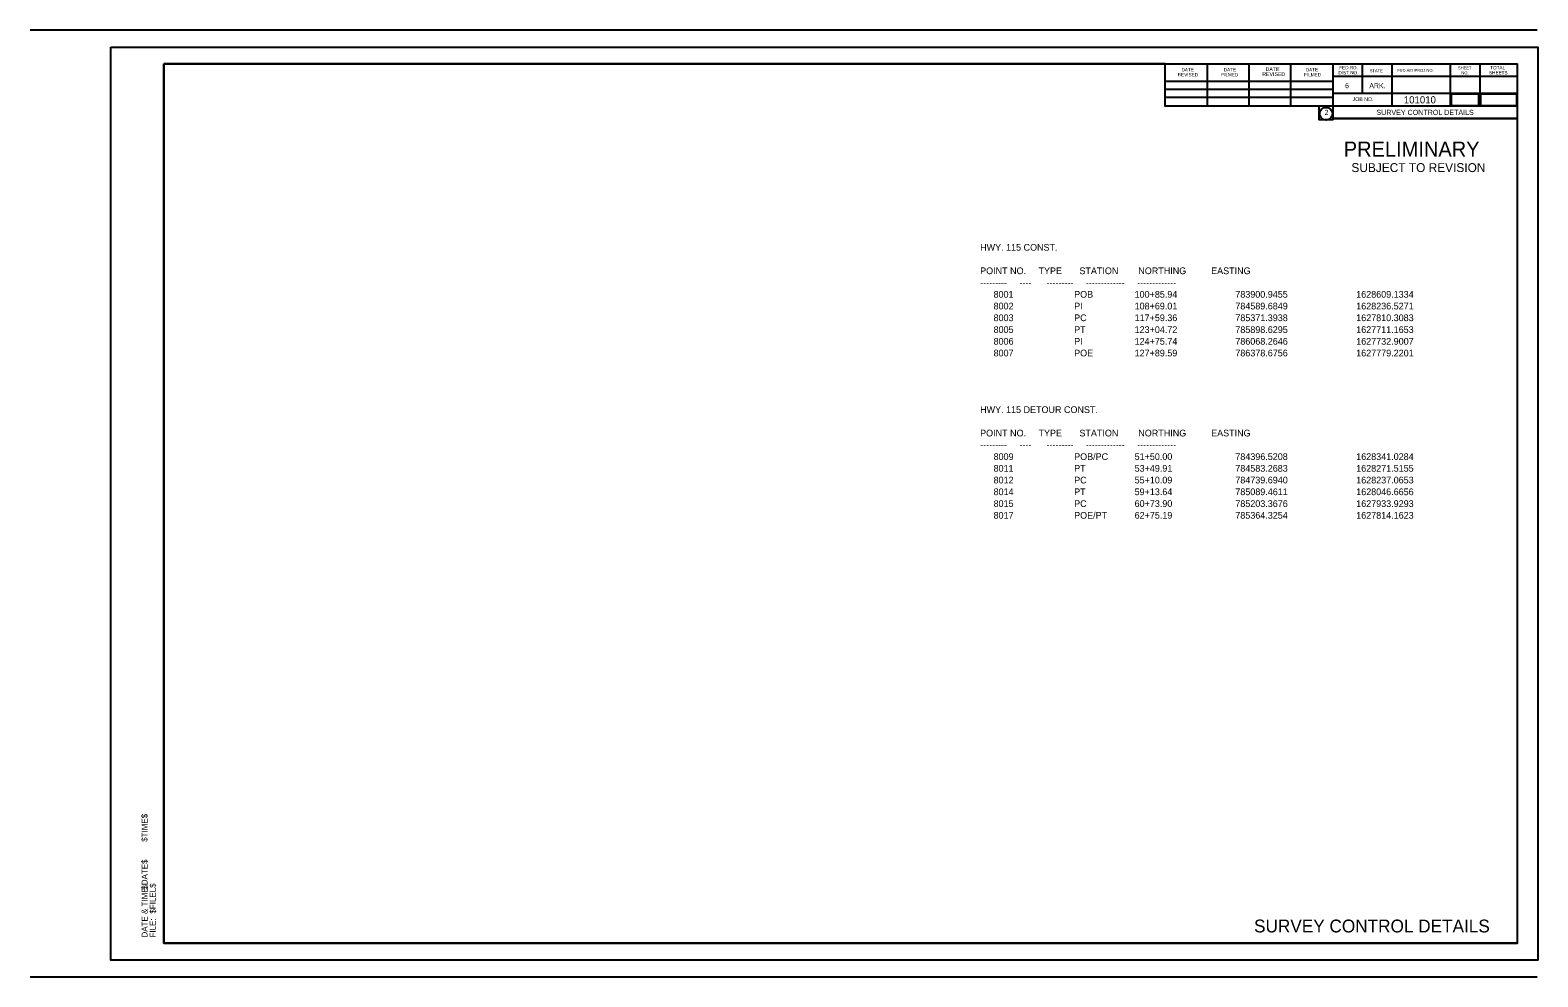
# Model space of a CAD drawing. Extents: x 3698 to 9589, y 10000 to 11106.
# Drawn here: x 3698 to 5459, y 10000 to 11106 of the extents above; entities that cross this region are included whole.
import ezdxf

# ---------------------------------------------------------------- set-up
doc = ezdxf.new("R2010")
doc.units = 0
for name, color, linetype in [('DATE', 7, 'Continuous'), ('GREEN_TXT', 7, 'Continuous'), ('R_Clearzone', 7, 'Continuous'), ('R_Driveway Slope', 7, 'Continuous'), ('R_Vert Alg LP', 7, 'Continuous'), ('RC Box Annot', 7, 'Continuous'), ('SEAL-INFO', 7, 'Continuous'), ('SIGNATURE', 7, 'Continuous')]:
    doc.layers.add(name, color=color, linetype=linetype)

msp = doc.modelspace()

# ---------------------------------------------------------------- linework, layer by layer
at = {"layer": 'DATE'}
msp.add_lwpolyline([(3854, 11066.7), (3854, 10039.4), (5434.9, 10039.4), (5434.9, 11002.7), (5219.4, 11002.7), (5219.4, 11001.3), (5203.3, 11001.3), (5203.3, 11017.3), (5023.6, 11017.3), (5023.6, 11066.7)], close=True, dxfattribs=at)
at = {"layer": 'GREEN_TXT'}
for p, q in [((5457.9, 11106.1), (3697.9, 11106.1)), ((3854, 11066.7), (5434.9, 11066.7)), ((3854, 10039.4), (3854, 11066.7)), ((4616.6, 11065.4), (4616.6, 11065.4)), ((4616.6, 11065.4), (4616.6, 11065.4)), ((5023.6, 11017.3), (5023.6, 11066.7)), ((5072.9, 11017.3), (5072.9, 11065.7)), ((5121.7, 11017.3), (5121.7, 11065.7)), ((5170.1, 11017.3), (5170.1, 11065.7)), ((5219.4, 11066.7), (5219.4, 11002.7)), ((5253.6, 11066.7), (5253.6, 11032)), ((5288.3, 11066.7), (5288.3, 11017.3)), ((5356.2, 11066.7), (5356.2, 11017.3)), ((5390.9, 11066.7), (5390.9, 11017.3)), ((5434.9, 10039.4), (5434.9, 11066.7)), ((5023.6, 11046.6), (5219.4, 11046.6)), ((5434.9, 11052), (5219.4, 11052)), ((5434.9, 11052.1), (5434.9, 11052.1)), ((5023.6, 11037.3), (5219.4, 11037.3)), ((5023.6, 11027.6), (5219.4, 11027.6)), ((5434.9, 11032), (5219.4, 11032)), ((5434.9, 11017.3), (5023.6, 11017.3)), ((5219.4, 11002.7), (5434.9, 11002.7)), ((5434.9, 10039.4), (3854, 10039.4)), ((3697.9, 10000), (5457.9, 10000))]:
    msp.add_line(p, q, dxfattribs=at)
msp.add_circle((5211.4, 11008.4), 7.33, dxfattribs=at)
at = {"layer": 'R_Clearzone'}
msp.add_lwpolyline([(3792, 11086.2), (5458.7, 11086.2), (5458.7, 10019.5), (3792, 10019.5)], close=True, dxfattribs=at)
at = {"layer": 'R_Driveway Slope'}
msp.add_lwpolyline([(5391.8, 11018), (5434.1, 11018), (5434.1, 11031.3), (5391.8, 11031.3)], close=True, dxfattribs=at)
at = {"layer": 'RC Box Annot'}
msp.add_lwpolyline([(5357.3, 11018), (5389.9, 11018), (5389.9, 11031.3), (5357.3, 11031.3)], close=True, dxfattribs=at)

# ---------------------------------------------------------------- texts
for s, height, p in [('$TIME$', 6.98, (3835, 10157.8)), ('$DATE$', 6.98, (3835, 10101.9)), ('$FILEL$', 6.98, (3844.6, 10073.9)), ('DATE & TIME:', 6.984, (3835, 10046)), ('FILE: ', 6.98, (3844.6, 10046))]:
    msp.add_text(s, height=height, rotation=90).set_placement(p)
at = {"layer": 'GREEN_TXT'}
for s, height, p in [('DATE', 3.91, (5042.6, 11057.9)), ('DATE', 3.91, (5091.9, 11057.9)), ('DATE', 4.4, (5140.8, 11058.4)), ('DATE', 3.91, (5187.7, 11057.9)), ('DIST.NO.', 3.91, (5225.8, 11054.4)), ('FED.RD.', 3.91, (5226.8, 11060.3)), ('STATE', 3.42, (5262.4, 11056.9)), ('FED.AID PROJ.NO.', 3.42, (5294.7, 11057.4)), ('SHEET', 3.42, (5365.5, 11060.3)), ('NO.', 3.42, (5369.4, 11054.4)), ('SHEETS', 3.91, (5401.7, 11054.4)), ('TOTAL', 3.91, (5403.1, 11060.3)), ('REVISED', 3.91, (5038.2, 11052)), ('FILMED', 3.91, (5089, 11052)), ('REVISED', 4.4, (5136.9, 11052.5)), ('FILMED', 3.91, (5185.7, 11052)), ('6', 5.86, (5233.6, 11038.3)), ('ARK.', 5.86, (5261.9, 11038.3)), ('JOB NO.', 4.4, (5242.4, 11023.2)), ('2', 5.86, (5209.7, 11007.1)), ('SURVEY CONTROL DETAILS', 15, (5127.3, 10051.9))]:
    msp.add_text(s, height=height, dxfattribs=at).set_placement(p)
at = {"layer": 'R_Vert Alg LP'}
for s, height, p in [('101010', 8.4, (5302.2, 11020.5)), ('SURVEY CONTROL DETAILS', 6, (5270.2, 11007))]:
    msp.add_text(s, height=height, dxfattribs=at).set_placement(p)
at = {"layer": 'SEAL-INFO'}
for s, height, p in [('PRELIMINARY', 17.5, (5232, 10958.4)), ('SUBJECT TO REVISION', 10.376, (5241, 10940.3))]:
    msp.add_text(s, height=height, dxfattribs=at).set_placement(p)
at = {"layer": 'SIGNATURE'}
for s, height, p in [('HWY. 115 CONST. ', 7.843, (4807.4, 10848.4)), ('POINT NO.     TYPE       STATION        NORTHING          EASTING ', 7.843, (4807.4, 10821)), ('---------     ----      ---------     -------------     ------------- ', 7.843, (4807.4, 10807.2)), ('8001', 7.84, (4823.1, 10793.5)), ('POB', 7.84, (4917.2, 10793.5)), ('100+85.94', 7.84, (4987.8, 10793.5)), ('783900.9455', 7.843, (5105.4, 10793.5)), ('1628609.1334 ', 7.843, (5246.6, 10793.5)), ('8002', 7.84, (4823.1, 10779.8)), ('PI', 7.84, (4917.2, 10779.8)), ('108+69.01', 7.84, (4987.8, 10779.8)), ('784589.6849', 7.843, (5105.4, 10779.8)), ('1628236.5271 ', 7.843, (5246.6, 10779.8)), ('8003', 7.84, (4823.1, 10766.1)), ('8005', 7.84, (4823.1, 10752.3)), ('PC', 7.84, (4917.2, 10766.1)), ('PT', 7.84, (4917.2, 10752.3)), ('117+59.36', 7.84, (4987.8, 10766.1)), ('123+04.72', 7.84, (4987.8, 10752.3)), ('785371.3938', 7.843, (5105.4, 10766.1)), ('785898.6295', 7.843, (5105.4, 10752.3)), ('1627810.3083 ', 7.843, (5246.6, 10766.1)), ('1627711.1653 ', 7.843, (5246.6, 10752.3)), ('8006', 7.84, (4823.1, 10738.6)), ('PI', 7.84, (4917.2, 10738.6)), ('124+75.74', 7.84, (4987.8, 10738.6)), ('786068.2646', 7.843, (5105.4, 10738.6)), ('1627732.9007 ', 7.843, (5246.6, 10738.6)), ('8007', 7.84, (4823.1, 10724.9)), ('POE', 7.84, (4917.2, 10724.9)), ('127+89.59', 7.84, (4987.8, 10724.9)), ('786378.6756', 7.843, (5105.4, 10724.9)), ('1627779.2201 ', 7.843, (5246.6, 10724.9)), ('HWY. 115 DETOUR CONST. ', 7.843, (4807.4, 10658.8)), ('POINT NO.     TYPE       STATION        NORTHING          EASTING ', 7.843, (4807.4, 10631.4)), ('---------     ----      ---------     -------------     ------------- ', 7.843, (4807.4, 10617.7)), ('8009', 7.84, (4823.1, 10603.9)), ('POB/PC', 7.84, (4917.2, 10603.9)), ('51+50.00', 7.84, (4987.8, 10603.9)), ('784396.5208', 7.843, (5105.4, 10603.9)), ('1628341.0284 ', 7.843, (5246.6, 10603.9)), ('8011', 7.84, (4823.1, 10590.2)), ('8012', 7.84, (4823.1, 10576.5)), ('PT', 7.84, (4917.2, 10590.2)), ('PC', 7.84, (4917.2, 10576.5)), ('53+49.91', 7.84, (4987.8, 10590.2)), ('55+10.09', 7.84, (4987.8, 10576.5)), ('784583.2683', 7.843, (5105.4, 10590.2)), ('784739.6940', 7.843, (5105.4, 10576.5)), ('1628271.5155 ', 7.843, (5246.6, 10590.2)), ('1628237.0653 ', 7.843, (5246.6, 10576.5)), ('8014', 7.84, (4823.1, 10562.8)), ('PT', 7.84, (4917.2, 10562.8)), ('59+13.64', 7.84, (4987.8, 10562.8)), ('785089.4611', 7.843, (5105.4, 10562.8)), ('1628046.6656', 7.843, (5246.6, 10562.8)), ('8015', 7.84, (4823.1, 10549)), ('PC', 7.84, (4917.2, 10549)), ('60+73.90', 7.84, (4987.8, 10549)), ('785203.3676', 7.843, (5105.4, 10549)), ('1627933.9293 ', 7.843, (5246.6, 10549)), ('8017', 7.84, (4823.1, 10535.3)), ('POE/PT', 7.84, (4917.2, 10535.3)), ('62+75.19', 7.84, (4987.8, 10535.3)), ('785364.3254', 7.843, (5105.4, 10535.3)), ('1627814.1623', 7.843, (5246.6, 10535.3))]:
    msp.add_text(s, height=height, dxfattribs=at).set_placement(p)

doc.saveas('drawing.dxf')
